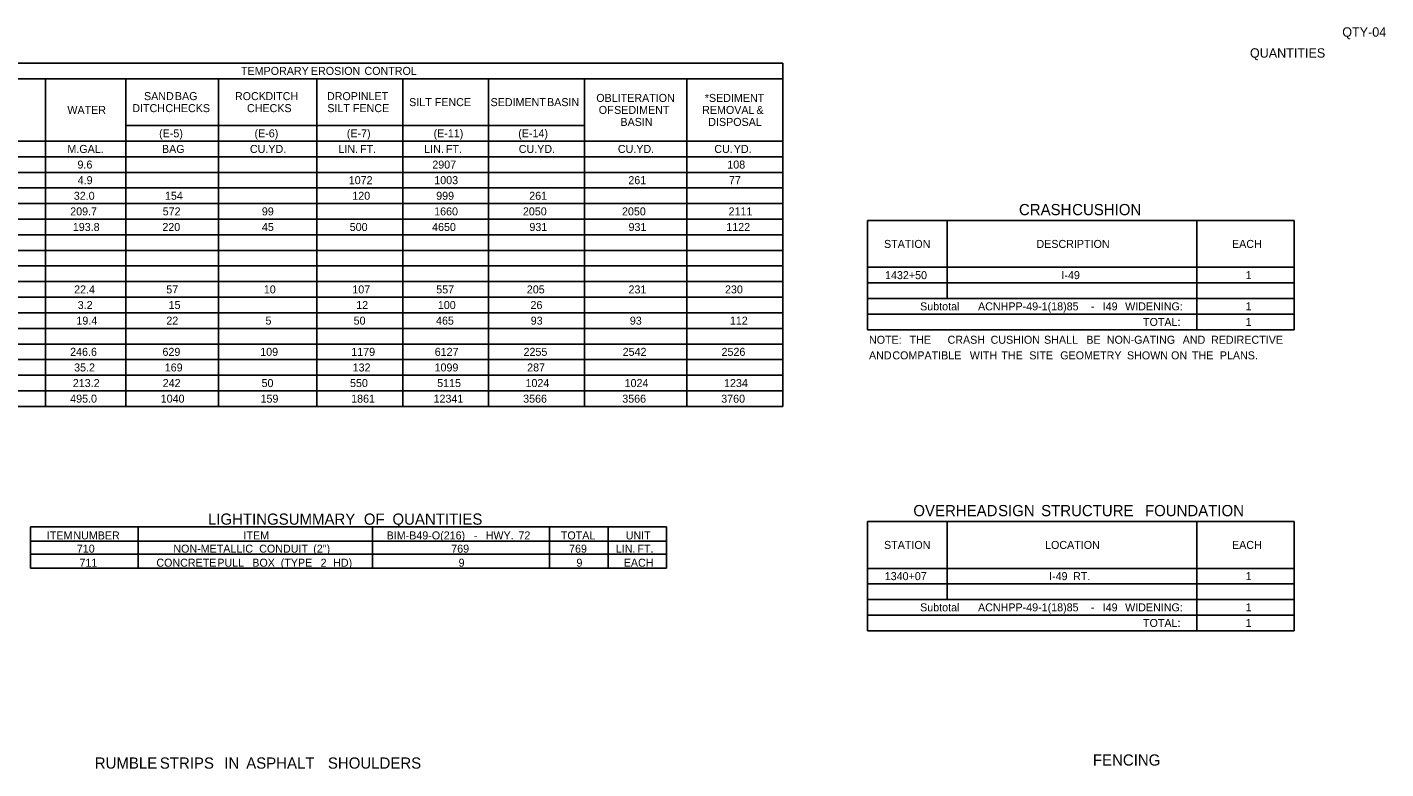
# Model space of a CAD drawing. Extents: x 1226589 to 1228130, y 151309 to 152305.
# Drawn here: x 1227261 to 1228109, y 151842 to 152305 of the extents above; entities that cross this region are included whole.
import ezdxf

# ---------------------------------------------------------------- set-up
doc = ezdxf.new("R2010")
doc.units = 0
doc.layers.add('R_Border', color=7, linetype='Continuous')
doc.layers.add('R_Dimension', color=7, linetype='Continuous')

msp = doc.modelspace()

# ---------------------------------------------------------------- linework, layer by layer
at = {"layer": 'R_Dimension'}
for p, q in [((1226588.59, 152283.05), (1227732.75, 152283.05)), ((1227732.75, 152068.55), (1227732.75, 152283.05)), ((1226906.44, 152273.3), (1227732.75, 152273.3)), ((1227272.06, 152068.55), (1227272.06, 152273.3)), ((1227322.27, 152068.55), (1227322.27, 152273.3)), ((1227380.29, 152068.55), (1227380.29, 152273.3)), ((1227441.71, 152068.55), (1227441.71, 152273.3)), ((1227495.34, 152068.55), (1227495.34, 152273.3)), ((1227548.96, 152068.55), (1227548.96, 152273.3)), ((1227608.92, 152068.55), (1227608.92, 152273.3)), ((1227672.79, 152068.55), (1227672.79, 152273.3)), ((1227322.27, 152244.05), (1227608.92, 152244.05)), ((1226906.44, 152234.3), (1227732.75, 152234.3)), ((1227608.92, 152234.3), (1227732.75, 152234.3)), ((1226588.59, 152224.55), (1227732.75, 152224.55)), ((1226588.59, 152214.8), (1227732.75, 152214.8)), ((1226588.59, 152205.05), (1227732.75, 152205.05)), ((1226588.59, 152195.3), (1227732.75, 152195.3)), ((1226588.59, 152185.55), (1227732.75, 152185.55)), ((1227785.63, 152184.72), (1228052.29, 152184.72)), ((1227785.63, 152116.47), (1227785.63, 152184.72)), ((1227835.35, 152135.97), (1227835.35, 152184.72)), ((1227991.35, 152116.47), (1227991.35, 152184.72)), ((1228052.29, 152116.47), (1228052.29, 152184.72)), ((1226588.59, 152175.8), (1227732.75, 152175.8)), ((1226588.59, 152166.05), (1227732.75, 152166.05)), ((1226588.59, 152156.3), (1227732.75, 152156.3)), ((1227785.63, 152155.47), (1228052.29, 152155.47)), ((1226588.59, 152146.55), (1227732.75, 152146.55)), ((1227785.63, 152145.72), (1228052.29, 152145.72)), ((1226588.59, 152136.8), (1227732.75, 152136.8)), ((1227785.63, 152135.97), (1228052.29, 152135.97)), ((1226588.59, 152127.05), (1227732.75, 152127.05)), ((1227785.63, 152126.22), (1228052.29, 152126.22)), ((1226588.59, 152117.3), (1227732.75, 152117.3)), ((1227785.63, 152116.47), (1228052.29, 152116.47)), ((1226588.59, 152107.55), (1227732.75, 152107.55)), ((1226588.59, 152097.8), (1227732.75, 152097.8)), ((1226588.59, 152088.05), (1227732.75, 152088.05)), ((1226588.59, 152078.3), (1227732.75, 152078.3)), ((1226588.59, 152068.55), (1227732.75, 152068.55)), ((1227262.8, 151993.28), (1227660.12, 151993.28)), ((1227262.8, 151967.44), (1227262.8, 151993.28)), ((1227330.08, 151967.44), (1227330.08, 151993.28)), ((1227476.33, 151967.44), (1227476.33, 151993.28)), ((1227586.99, 151967.44), (1227586.99, 151993.28)), ((1227623.55, 151967.44), (1227623.55, 151993.28)), ((1227660.12, 151967.44), (1227660.12, 151993.28)), ((1227785.63, 151996.67), (1228052.29, 151996.67)), ((1227785.63, 151928.42), (1227785.63, 151996.67)), ((1227835.35, 151947.92), (1227835.35, 151996.67)), ((1227991.35, 151928.42), (1227991.35, 151996.67)), ((1228052.29, 151928.42), (1228052.29, 151996.67)), ((1227262.8, 151984.5), (1227660.12, 151984.5)), ((1227262.8, 151984.5), (1227660.12, 151984.5)), ((1227262.8, 151976.21), (1227660.12, 151976.21)), ((1227262.8, 151967.44), (1227660.12, 151967.44)), ((1227785.63, 151967.42), (1228052.29, 151967.42)), ((1227785.63, 151957.67), (1228052.29, 151957.67)), ((1227785.63, 151947.92), (1228052.29, 151947.92)), ((1227785.63, 151938.17), (1228052.29, 151938.17)), ((1227785.63, 151928.42), (1228052.29, 151928.42))]:
    msp.add_line(p, q, dxfattribs=at)

# ---------------------------------------------------------------- texts
at = {"layer": 'R_Border'}
for s, height, p in [('QTY-04', 5.861, (1228082.24, 152299.55)), ('QUANTITIES', 5.862, (1228024.56, 152286.45))]:
    msp.add_text(s, height=height, dxfattribs=at).set_placement(p)
at = {"layer": 'R_Dimension'}
for s, height, p in [('TEMPORARY', 5, (1227394.28, 152275.67)), (' EROSION', 5, (1227436.09, 152275.67)), (' CONTROL', 5, (1227469.55, 152275.67)), ('SAND', 5, (1227333.7, 152259.92)), (' BAG', 5, (1227351.14, 152259.92)), ('ROCK', 5, (1227390.51, 152259.92)), (' DITCH', 5, (1227407.67, 152259.92)), ('DROP', 5, (1227447.99, 152259.92)), (' INLET', 5, (1227465.43, 152259.92)), ('WATER', 5, (1227285.81, 152251.3)), ('DITCH', 5, (1227326.38, 152252.42)), (' CHECKS', 5, (1227345.2, 152252.42)), ('CHECKS', 5, (1227398.01, 152252.42)), ('SILT', 5, (1227448.21, 152252.42)), (' FENCE', 5, (1227462.34, 152252.42)), ('SILT', 5, (1227499.33, 152256.17)), (' FENCE', 5, (1227513.47, 152256.17)), ('SEDIMENT', 5, (1227550.18, 152256.17)), (' BASIN', 5, (1227583.61, 152256.17)), ('OBLITERATION', 5, (1227616.23, 152258.8)), ('OF', 5, (1227617.77, 152251.3)), (' SEDIMENT', 5, (1227625.52, 152251.3)), ('REMOVAL', 5, (1227682.36, 152251.3)), ('*SEDIMENT', 5, (1227684.01, 152258.8)), (' &', 5, (1227714.4, 152251.3)), ('BASIN', 5, (1227631.31, 152243.8)), ('DISPOSAL', 5, (1227686.19, 152243.8)), ('(E-5)', 5, (1227343.13, 152236.67)), ('(E-6)', 5, (1227402.73, 152236.67)), ('(E-7)', 5, (1227460.38, 152236.67)), ('(E-11)', 5, (1227514.59, 152236.67)), ('(E-14)', 5, (1227567.47, 152236.67)), ('M.GAL.', 5, (1227285.83, 152226.92)), ('BAG', 5, (1227344.92, 152226.92)), ('CU.YD.', 5, (1227399.86, 152226.92)), ('LIN.', 5, (1227455.12, 152226.92)), (' FT.', 5, (1227466.77, 152226.92)), ('LIN.', 5, (1227508.74, 152226.92)), (' FT.', 5, (1227520.4, 152226.92)), ('CU.YD.', 5, (1227567.8, 152226.92)), ('CU.YD.', 5, (1227629.71, 152226.92)), ('CU.', 5, (1227689.95, 152226.92)), (' YD.', 5, (1227700.27, 152226.92)), ('9.6', 5, (1227292.15, 152217.17)), ('2907', 5, (1227513.8, 152217.17)), ('108', 5, (1227698.08, 152217.17)), ('4.9', 5, (1227292.27, 152207.42)), ('1072', 5, (1227461.6, 152207.42)), ('1003', 5, (1227515.02, 152207.42)), ('261', 5, (1227636.25, 152207.42)), ('77', 5, (1227699.11, 152207.42)), ('32.0', 5, (1227289.83, 152197.67)), ('154', 5, (1227346.79, 152197.67)), ('120', 5, (1227463.82, 152197.67)), ('999', 5, (1227516.22, 152197.67)), ('261', 5, (1227574.34, 152197.67)), ('209.7', 5, (1227287.6, 152187.92)), ('572', 5, (1227345.38, 152187.92)), ('99', 5, (1227407.32, 152187.92)), ('1660', 5, (1227514.96, 152187.92)), ('2050', 5, (1227570.38, 152187.92)), ('2050', 5, (1227632.29, 152187.92)), ('2111', 5, (1227698.87, 152187.92)), ('CRASH', 7, (1227880.27, 152188.04)), (' CUSHION', 7, (1227910.91, 152188.04)), ('193.8', 5, (1227289.22, 152178.17)), ('220', 5, (1227345.16, 152178.17)), ('45', 5, (1227407.34, 152178.17)), ('500', 5, (1227462.21, 152178.17)), ('4650', 5, (1227513.67, 152178.17)), ('931', 5, (1227574.46, 152178.17)), ('931', 5, (1227636.37, 152178.17)), ('1122', 5, (1227697.45, 152178.17)), ('STATION', 5, (1227795.98, 152167.59)), ('DESCRIPTION', 5, (1227891.21, 152167.59)), ('EACH', 5, (1228013.36, 152167.59)), ('1432+50', 5, (1227796.61, 152148.09)), ('I-49', 5, (1227906.8, 152148.09)), ('1', 5, (1228021.82, 152148.09)), ('22.4', 5, (1227290.04, 152139.17)), ('57', 5, (1227347.62, 152139.17)), ('10', 5, (1227408.54, 152139.17)), ('107', 5, (1227463.84, 152139.17)), ('557', 5, (1227516.24, 152139.17)), ('205', 5, (1227572.84, 152139.17)), ('231', 5, (1227636.37, 152139.17)), ('230', 5, (1227696.65, 152139.17)), ('3.2', 5, (1227292.29, 152129.42)), ('15', 5, (1227349.04, 152129.42)), ('12', 5, (1227466.28, 152129.42)), ('100', 5, (1227517.25, 152129.42)), ('26', 5, (1227575.14, 152129.42)), ('Subtotal', 5, (1227818.52, 152128.59)), (' ACNHPP-49-1(18)85', 5, (1227852.85, 152128.59)), (' -', 5, (1227923.29, 152128.59)), (' I49', 5, (1227930.73, 152128.59)), (' WIDENING:', 5, (1227944.74, 152128.59)), ('1', 5, (1228021.82, 152128.59)), ('19.4', 5, (1227291.46, 152119.67)), ('22', 5, (1227347.62, 152119.67)), ('5', 5, (1227409.58, 152119.67)), ('50', 5, (1227464.65, 152119.67)), ('465', 5, (1227516.13, 152119.67)), ('93', 5, (1227575.28, 152119.67)), ('93', 5, (1227637.19, 152119.67)), ('112', 5, (1227699.7, 152119.67)), ('TOTAL:', 5, (1227957.77, 152118.84)), ('1', 5, (1228021.82, 152118.84)), ('NOTE:', 5, (1227786.6, 152107.72)), ('   THE', 5, (1227806.37, 152107.72)), (' CRASH', 5, (1227833.81, 152107.72)), (' CUSHION', 5, (1227860.7, 152107.72)), (' SHALL', 5, (1227894.08, 152107.72)), (' BE', 5, (1227920.5, 152107.72)), (' NON-GATING', 5, (1227933.3, 152107.72)), (' AND', 5, (1227980.7, 152107.72)), (' REDIRECTIVE', 5, (1227998.41, 152107.72)), ('246.6', 5, (1227287.54, 152100.17)), ('629', 5, (1227345.24, 152100.17)), ('109', 5, (1227406.3, 152100.17)), ('1179', 5, (1227463.19, 152100.17)), ('6127', 5, (1227515.3, 152100.17)), ('2255', 5, (1227570.79, 152100.17)), ('2542', 5, (1227632.71, 152100.17)), ('2526', 5, (1227694.48, 152100.17)), ('35.2', 5, (1227290.04, 152090.42)), ('169', 5, (1227346.66, 152090.42)), ('132', 5, (1227464.04, 152090.42)), ('1099', 5, (1227515.2, 152090.42)), ('287', 5, (1227573.04, 152090.42)), ('AND', 5, (1227786.6, 152097.97)), (' COMPATIBLE', 5, (1227799.32, 152097.97)), (' WITH', 5, (1227847.7, 152097.97)), (' THE', 5, (1227867.43, 152097.97)), (' SITE', 5, (1227884.87, 152097.97)), (' GEOMETRY', 5, (1227904.2, 152097.97)), (' SHOWN', 5, (1227945.89, 152097.97)), (' ON', 5, (1227973.45, 152097.97)), (' THE', 5, (1227986.44, 152097.97)), (' PLANS.', 5, (1228003.89, 152097.97)), ('213.2', 5, (1227289.22, 152080.67)), ('242', 5, (1227345.38, 152080.67)), ('50', 5, (1227407.12, 152080.67)), ('550', 5, (1227462.4, 152080.67)), ('5115', 5, (1227516.83, 152080.67)), ('1024', 5, (1227572.01, 152080.67)), ('1024', 5, (1227633.93, 152080.67)), ('1234', 5, (1227696.04, 152080.67)), ('495.0', 5, (1227287.58, 152070.92)), ('1040', 5, (1227344.14, 152070.92)), ('159', 5, (1227406.49, 152070.92)), ('1861', 5, (1227463.09, 152070.92)), ('12341', 5, (1227514.59, 152070.92)), ('3566', 5, (1227570.54, 152070.92)), ('3566', 5, (1227632.45, 152070.92)), ('3760', 5, (1227694.28, 152070.92)), ('LIGHTING', 7, (1227373.63, 151994.68)), (' SUMMARY', 7, (1227415.24, 151994.68)), (' OF', 7, (1227468.43, 151994.68)), (' QUANTITIES', 7, (1227486.29, 151994.68)), ('OVERHEAD', 7, (1227814.29, 152000)), (' SIGN', 7, (1227864.61, 152000)), (' STRUCTURE', 7, (1227891.51, 152000)), (' FOUNDATION', 7, (1227956.38, 152000)), ('ITEM', 5, (1227272.98, 151985.5)), (' NUMBER', 5, (1227287.7, 151985.5)), ('ITEM', 5, (1227395.84, 151985.5)), ('BIM-B49-O(216)', 5, (1227485.26, 151985.5)), (' -', 5, (1227537.86, 151985.5)), (' HWY.', 5, (1227545.3, 151985.5)), (' 72', 5, (1227565.74, 151985.5)), ('TOTAL', 5, (1227594.09, 151985.5)), ('UNIT', 5, (1227634.61, 151985.5)), ('STATION', 5, (1227795.98, 151979.55)), ('LOCATION', 5, (1227896.6, 151979.55)), ('EACH', 5, (1228013.36, 151979.55)), ('710', 5, (1227291.74, 151977.21)), ('NON-METALLIC', 5, (1227352.02, 151977.21)), (' CONDUIT', 5, (1227403.79, 151977.21)), (' (2")', 5, (1227437.57, 151977.21)), ('769', 5, (1227525.62, 151977.21)), ('769', 5, (1227599.23, 151977.21)), ('LIN.', 5, (1227628.43, 151977.21)), (' FT.', 5, (1227640.08, 151977.21)), ('711', 5, (1227293.37, 151968.44)), ('CONCRETE', 5, (1227341.41, 151968.44)), (' PULL', 5, (1227377.63, 151968.44)), (' BOX', 5, (1227399.48, 151968.44)), (' (TYPE', 5, (1227417.24, 151968.44)), (' 2', 5, (1227442.16, 151968.44)), (' HD)', 5, (1227450, 151968.44)), ('9', 5, (1227530.22, 151968.44)), ('9', 5, (1227603.84, 151968.44)), ('EACH', 5, (1227633.37, 151968.44)), ('1340+07', 5, (1227796.43, 151960.05)), ('I-49', 5, (1227899.1, 151960.05)), (' RT.', 5, (1227912.21, 151960.05)), ('1', 5, (1228021.82, 151960.05)), ('Subtotal', 5, (1227818.52, 151940.55)), (' ACNHPP-49-1(18)85', 5, (1227852.85, 151940.55)), (' -', 5, (1227923.29, 151940.55)), (' I49', 5, (1227930.73, 151940.55)), (' WIDENING:', 5, (1227944.74, 151940.55)), ('1', 5, (1228021.82, 151940.55)), ('TOTAL:', 5, (1227957.77, 151930.8)), ('1', 5, (1228021.82, 151930.8)), ('RUMBLE', 7, (1227302.93, 151842.28)), (' STRIPS', 7, (1227340.97, 151842.28)), (' IN', 7, (1227381.26, 151842.28)), (' ASPHALT', 7, (1227394.93, 151842.28)), (' SHOULDERS', 7, (1227445.97, 151842.28)), ('FENCING', 7, (1227926.48, 151844.2))]:
    msp.add_text(s, height=height, dxfattribs=at).set_placement(p)

doc.saveas('drawing.dxf')
